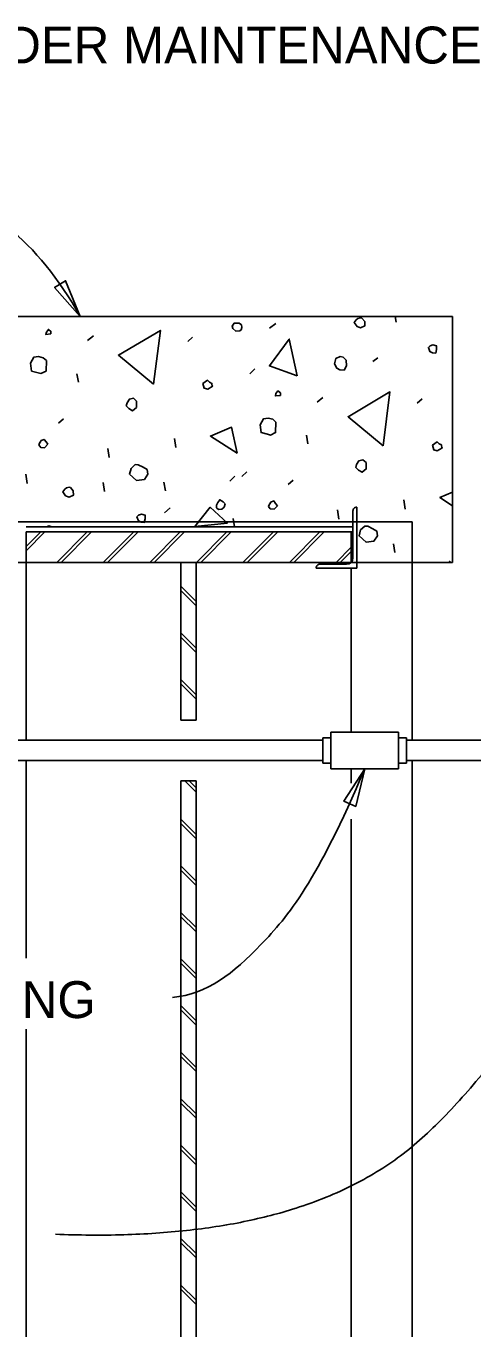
# Model space of a CAD drawing. Extents: x -1660015.2 to -1659984.9, y 2580594.2 to 2580616.7.
# Drawn here: x -1659990.89 to -1659989.06, y 2580599.91 to 2580605.25 of the extents above; entities that cross this region are included whole.
import ezdxf

# ---------------------------------------------------------------- set-up
doc = ezdxf.new("R2010")
doc.units = 0
for name, color, linetype in [('Default', 7, 'Continuous'), ('Miscellaneous', 7, 'Continuous'), ('Miscellaneous3', 7, 'Continuous'), ('PlotBorder_dp', 7, 'Continuous'), ('SheetLines_dp', 7, 'Continuous'), ('SteelGirder', 7, 'Continuous')]:
    doc.layers.add(name, color=color, linetype=linetype)

msp = doc.modelspace()

# ---------------------------------------------------------------- linework, layer by layer
at = {"layer": 'Default'}
for p, q in [((-1659989.3053, 2580603.2147), (-1659991.2021, 2580603.2147)), ((-1659989.3053, 2580603.2147), (-1659989.3053, 2580603.0479)), ((-1659990.8887, 2580603.048), (-1659991.1415, 2580603.048)), ((-1659989.6716, 2580602.3289), (-1659989.6716, 2580602.2247)), ((-1659989.6716, 2580602.3289), (-1659989.6382, 2580602.3289)), ((-1659989.6382, 2580602.3519), (-1659989.6382, 2580602.202)), ((-1659989.6381, 2580602.352), (-1659989.3607, 2580602.352)), ((-1659989.3607, 2580602.3518), (-1659989.3607, 2580602.2019)), ((-1659989.3273, 2580602.3289), (-1659989.3607, 2580602.3289)), ((-1659989.3273, 2580602.3289), (-1659989.3273, 2580602.2247)), ((-1659989.6715, 2580602.3186), (-1659991.6974, 2580602.3186)), ((-1659986.2685, 2580602.3187), (-1659989.3273, 2580602.3187)), ((-1659989.6716, 2580602.2353), (-1659991.6974, 2580602.2353)), ((-1659989.6716, 2580602.2247), (-1659989.6382, 2580602.2247)), ((-1659989.3273, 2580602.2247), (-1659989.3607, 2580602.2247)), ((-1659986.2685, 2580602.2354), (-1659989.3273, 2580602.2354)), ((-1659989.6381, 2580602.2021), (-1659989.3607, 2580602.2021))]:
    msp.add_line(p, q, dxfattribs=at)
at = {"layer": 'Miscellaneous'}
for p, q in [((-1659989.371, 2580604.0323), (-1659989.3744, 2580604.056)), ((-1659990.6126, 2580603.9767), (-1659990.636, 2580603.9571)), ((-1659989.8641, 2580604.0272), (-1659989.8899, 2580604.0082)), ((-1659990.2052, 2580603.9711), (-1659990.2255, 2580603.9532)), ((-1659989.4462, 2580603.8868), (-1659989.4658, 2580603.8713)), ((-1659990.6741, 2580603.7861), (-1659990.6801, 2580603.8214)), ((-1659989.9503, 2580603.8407), (-1659989.9712, 2580603.8204)), ((-1659989.6709, 2580603.7244), (-1659989.6942, 2580603.7048)), ((-1659989.2634, 2580603.7187), (-1659989.2838, 2580603.7009)), ((-1659990.7348, 2580603.6368), (-1659990.7551, 2580603.6189)), ((-1659990.2747, 2580603.5187), (-1659990.2801, 2580603.5563)), ((-1659989.7323, 2580603.5338), (-1659989.7384, 2580603.5691)), ((-1659990.547, 2580603.4778), (-1659990.5525, 2580603.5154)), ((-1659990.8836, 2580603.3712), (-1659990.889, 2580603.4089)), ((-1659990.0317, 2580603.4018), (-1659990.0526, 2580603.3815)), ((-1659989.9828, 2580603.4197), (-1659990.0038, 2580603.3995)), ((-1659990.5664, 2580603.338), (-1659990.5718, 2580603.3757)), ((-1659990.3171, 2580603.3411), (-1659990.3232, 2580603.3764)), ((-1659989.793, 2580603.3844), (-1659989.8133, 2580603.3666)), ((-1659989.3329, 2580603.2663), (-1659989.3383, 2580603.304)), ((-1659990.297, 2580603.271), (-1659990.3204, 2580603.2514)), ((-1659989.6053, 2580603.2254), (-1659989.6107, 2580603.2631)), ((-1659989.5476, 2580603.2591), (-1659989.5476, 2580603.0664)), ((-1659989.532, 2580603.0247), (-1659989.532, 2580603.2747)), ((-1659990.8887, 2580603.1937), (-1659989.5476, 2580603.1937)), ((-1659990.0336, 2580603.1937), (-1659990.0394, 2580603.2279)), ((-1659990.8887, 2580603.1128), (-1659990.8285, 2580603.1729)), ((-1659990.8887, 2580603.0951), (-1659990.8109, 2580603.1729)), ((-1659990.7626, 2580603.0479), (-1659990.6376, 2580603.1729)), ((-1659990.7449, 2580603.0479), (-1659990.6199, 2580603.1729)), ((-1659990.5717, 2580603.0479), (-1659990.4467, 2580603.1729)), ((-1659990.554, 2580603.0479), (-1659990.429, 2580603.1729)), ((-1659990.3808, 2580603.0479), (-1659990.2558, 2580603.1729)), ((-1659990.3631, 2580603.0479), (-1659990.2381, 2580603.1729)), ((-1659990.1899, 2580603.0479), (-1659990.0649, 2580603.1729)), ((-1659990.1722, 2580603.0479), (-1659990.0472, 2580603.1729)), ((-1659989.9989, 2580603.0479), (-1659989.8739, 2580603.1729)), ((-1659989.9813, 2580603.0479), (-1659989.8563, 2580603.1729)), ((-1659989.808, 2580603.0479), (-1659989.683, 2580603.1729)), ((-1659989.7903, 2580603.0479), (-1659989.6653, 2580603.1729)), ((-1659989.5476, 2580603.1729), (-1659989.5553, 2580603.1729)), ((-1659989.3753, 2580603.0887), (-1659989.3814, 2580603.124)), ((-1659989.6171, 2580603.0479), (-1659989.5553, 2580603.1097)), ((-1659989.5994, 2580603.0479), (-1659989.5553, 2580603.0921)), ((-1659989.6987, 2580603.0247), (-1659989.532, 2580603.0247)), ((-1659989.5737, 2580603.0403), (-1659989.683, 2580603.0403)), ((-1659990.1908, 2580602.8874), (-1659990.2531, 2580602.9498)), ((-1659990.1908, 2580602.8697), (-1659990.2531, 2580602.9321)), ((-1659990.1908, 2580602.6965), (-1659990.2531, 2580602.7589)), ((-1659990.1908, 2580602.6788), (-1659990.2531, 2580602.7412)), ((-1659990.1908, 2580602.5056), (-1659990.2531, 2580602.568)), ((-1659990.1908, 2580602.4879), (-1659990.2531, 2580602.5503)), ((-1659990.1908, 2580602.106), (-1659990.2367, 2580602.152)), ((-1659990.1908, 2580602.1237), (-1659990.219, 2580602.152)), ((-1659990.1908, 2580601.9328), (-1659990.2531, 2580601.9952)), ((-1659990.1908, 2580601.9151), (-1659990.2531, 2580601.9775)), ((-1659990.1908, 2580601.7419), (-1659990.2531, 2580601.8043)), ((-1659990.1908, 2580601.7242), (-1659990.2531, 2580601.7866)), ((-1659990.1908, 2580601.551), (-1659990.2531, 2580601.6134)), ((-1659990.1908, 2580601.5333), (-1659990.2531, 2580601.5957)), ((-1659990.1908, 2580601.3601), (-1659990.2531, 2580601.4224)), ((-1659990.1908, 2580601.3424), (-1659990.2531, 2580601.4048)), ((-1659990.1908, 2580601.1691), (-1659990.2531, 2580601.2315)), ((-1659990.1908, 2580601.1515), (-1659990.2531, 2580601.2139)), ((-1659990.1908, 2580600.9782), (-1659990.2531, 2580601.0406)), ((-1659990.1908, 2580600.9605), (-1659990.2531, 2580601.0229)), ((-1659990.1908, 2580600.7873), (-1659990.2531, 2580600.8497)), ((-1659990.1908, 2580600.7696), (-1659990.2531, 2580600.832)), ((-1659990.1908, 2580600.5964), (-1659990.2531, 2580600.6588)), ((-1659990.1908, 2580600.5787), (-1659990.2531, 2580600.6411)), ((-1659990.1908, 2580600.4055), (-1659990.2531, 2580600.4679)), ((-1659990.1908, 2580600.3878), (-1659990.2531, 2580600.4502)), ((-1659990.1908, 2580600.2145), (-1659990.2531, 2580600.2769)), ((-1659990.1908, 2580600.1969), (-1659990.2531, 2580600.2593)), ((-1659990.1908, 2580600.0236), (-1659990.2531, 2580600.086)), ((-1659990.1908, 2580600.0059), (-1659990.2531, 2580600.0683))]:
    msp.add_line(p, q, dxfattribs=at)
for points in [[(-1659989.4995, 2580604.0356), (-1659989.4992, 2580604.0174), (-1659989.5169, 2580604.0092), (-1659989.5307, 2580604.0155), (-1659989.542, 2580604.0315), (-1659989.5339, 2580604.0423), (-1659989.5271, 2580604.0482), (-1659989.5162, 2580604.0505), (-1659989.5114, 2580604.0492), (-1659989.4995, 2580604.0356)], [(-1659990.7866, 2580603.9845), (-1659990.8078, 2580603.9824), (-1659990.8052, 2580603.9921), (-1659990.7972, 2580604.0029), (-1659990.7864, 2580603.9948), (-1659990.7866, 2580603.9845)], [(-1659990.3655, 2580603.7785), (-1659990.3376, 2580603.9988), (-1659990.5097, 2580603.8974), (-1659990.3655, 2580603.7785)], [(-1659990.0058, 2580604.0005), (-1659990.0119, 2580603.9969), (-1659990.0277, 2580603.996), (-1659990.0403, 2580604.0071), (-1659990.0432, 2580604.0157), (-1659990.0344, 2580604.0289), (-1659990.0138, 2580604.0285), (-1659990.0055, 2580604.0211), (-1659990.0032, 2580604.0101), (-1659990.0058, 2580604.0005)], [(-1659989.7767, 2580603.8123), (-1659989.8087, 2580603.9632), (-1659989.89, 2580603.853), (-1659989.7767, 2580603.8123)], [(-1659989.2043, 2580603.9203), (-1659989.2081, 2580603.9058), (-1659989.2209, 2580603.9066), (-1659989.2323, 2580603.9123), (-1659989.2381, 2580603.9293), (-1659989.2313, 2580603.9353), (-1659989.2197, 2580603.94), (-1659989.2052, 2580603.9361), (-1659989.2043, 2580603.9203)], [(-1659990.8054, 2580603.8757), (-1659990.8067, 2580603.832), (-1659990.8275, 2580603.8221), (-1659990.8396, 2580603.8253), (-1659990.8661, 2580603.8324), (-1659990.8704, 2580603.8646), (-1659990.8561, 2580603.8893), (-1659990.8372, 2580603.892), (-1659990.8179, 2580603.8868), (-1659990.8054, 2580603.8757)], [(-1659989.5755, 2580603.8774), (-1659989.5741, 2580603.8537), (-1659989.5841, 2580603.8357), (-1659989.6016, 2580603.8378), (-1659989.6131, 2580603.8435), (-1659989.6237, 2580603.8619), (-1659989.6179, 2580603.8836), (-1659989.6001, 2580603.8918), (-1659989.5881, 2580603.8885), (-1659989.5755, 2580603.8774)], [(-1659990.1249, 2580603.7684), (-1659990.1433, 2580603.7578), (-1659990.1578, 2580603.7617), (-1659990.1629, 2580603.7812), (-1659990.1439, 2580603.7942), (-1659990.1355, 2580603.7868), (-1659990.1265, 2580603.7818), (-1659990.1249, 2580603.7684), (-1659990.1236, 2580603.7732)], [(-1659990.4353, 2580603.7015), (-1659990.435, 2580603.6833), (-1659990.4516, 2580603.6696), (-1659990.4673, 2580603.679), (-1659990.4774, 2580603.6894), (-1659990.4742, 2580603.7015), (-1659990.4648, 2580603.7171), (-1659990.4484, 2580603.7205), (-1659990.4358, 2580603.7094), (-1659990.4353, 2580603.7015)], [(-1659989.8448, 2580603.7322), (-1659989.866, 2580603.7301), (-1659989.8634, 2580603.7397), (-1659989.8554, 2580603.7505), (-1659989.8446, 2580603.7425), (-1659989.8448, 2580603.7322)], [(-1659989.4237, 2580603.5262), (-1659989.3958, 2580603.7464), (-1659989.5679, 2580603.645), (-1659989.4237, 2580603.5262)], [(-1659989.8636, 2580603.6233), (-1659989.8649, 2580603.5797), (-1659989.8857, 2580603.5697), (-1659989.8978, 2580603.573), (-1659989.9243, 2580603.5801), (-1659989.9287, 2580603.6123), (-1659989.9143, 2580603.6369), (-1659989.8955, 2580603.6396), (-1659989.8761, 2580603.6344), (-1659989.8636, 2580603.6233)], [(-1659990.799, 2580603.5323), (-1659990.8132, 2580603.518), (-1659990.8283, 2580603.5195), (-1659990.8361, 2580603.5293), (-1659990.8348, 2580603.5341), (-1659990.826, 2580603.5473), (-1659990.8144, 2580603.552), (-1659990.8067, 2580603.5422), (-1659990.799, 2580603.5323)], [(-1659990.0222, 2580603.495), (-1659990.0453, 2580603.6021), (-1659990.1326, 2580603.566), (-1659990.0222, 2580603.495)], [(-1659989.1832, 2580603.5161), (-1659989.2015, 2580603.5055), (-1659989.216, 2580603.5093), (-1659989.2212, 2580603.5288), (-1659989.2021, 2580603.5418), (-1659989.1938, 2580603.5344), (-1659989.1848, 2580603.5294), (-1659989.1832, 2580603.5161), (-1659989.1819, 2580603.5209)], [(-1659990.3893, 2580603.4096), (-1659990.403, 2580603.3874), (-1659990.4352, 2580603.3831), (-1659990.4645, 2580603.4091), (-1659990.458, 2580603.4332), (-1659990.4408, 2580603.4493), (-1659990.4281, 2580603.4485), (-1659990.4076, 2580603.4378), (-1659990.392, 2580603.4284), (-1659990.3893, 2580603.4096)], [(-1659989.4936, 2580603.4491), (-1659989.4933, 2580603.4309), (-1659989.5099, 2580603.4172), (-1659989.5255, 2580603.4266), (-1659989.5356, 2580603.4371), (-1659989.5324, 2580603.4492), (-1659989.523, 2580603.4648), (-1659989.5066, 2580603.4681), (-1659989.494, 2580603.457), (-1659989.4936, 2580603.4491)], [(-1659990.6949, 2580603.3414), (-1659990.6946, 2580603.3232), (-1659990.7123, 2580603.315), (-1659990.7262, 2580603.3213), (-1659990.7374, 2580603.3372), (-1659990.7293, 2580603.348), (-1659990.7226, 2580603.354), (-1659990.7116, 2580603.3562), (-1659990.7068, 2580603.3549), (-1659990.6949, 2580603.3414)], [(-1659989.1387, 2580603.3352), (-1659989.1908, 2580603.3136), (-1659989.1387, 2580603.2801)], [(-1659990.0763, 2580603.274), (-1659990.0861, 2580603.2662), (-1659990.0995, 2580603.2646), (-1659990.1078, 2580603.2721), (-1659990.1076, 2580603.2824), (-1659990.102, 2580603.2938), (-1659990.0939, 2580603.3046), (-1659990.0807, 2580603.2959), (-1659990.0724, 2580603.2884), (-1659990.0763, 2580603.274)], [(-1659989.8572, 2580603.28), (-1659989.8714, 2580603.2657), (-1659989.8866, 2580603.2671), (-1659989.8943, 2580603.277), (-1659989.893, 2580603.2818), (-1659989.8843, 2580603.295), (-1659989.8727, 2580603.2996), (-1659989.865, 2580603.2898), (-1659989.8572, 2580603.28)], [(-1659990.3997, 2580603.226), (-1659990.4036, 2580603.2115), (-1659990.4163, 2580603.2124), (-1659990.4277, 2580603.218), (-1659990.4335, 2580603.2351), (-1659990.4267, 2580603.241), (-1659990.4151, 2580603.2457), (-1659990.4006, 2580603.2418), (-1659990.3997, 2580603.226)], [(-1659990.0628, 2580603.2082), (-1659990.1333, 2580603.2737), (-1659990.1958, 2580603.1947), (-1659990.0628, 2580603.2082)], [(-1659990.8037, 2580603.1937), (-1659990.7955, 2580603.1975), (-1659990.7835, 2580603.1943), (-1659990.7829, 2580603.1937)], [(-1659989.4475, 2580603.1573), (-1659989.4613, 2580603.135), (-1659989.4935, 2580603.1307), (-1659989.5227, 2580603.1567), (-1659989.5163, 2580603.1809), (-1659989.499, 2580603.1969), (-1659989.4863, 2580603.1961), (-1659989.4659, 2580603.1855), (-1659989.4503, 2580603.1761), (-1659989.4475, 2580603.1573)], [(-1659989.1554, 2580603.0479), (-1659989.1522, 2580603.0522), (-1659989.1456, 2580603.0479)]]:
    msp.add_lwpolyline(points, dxfattribs=at)
for centre, radius, start, end in [((-1659989.532, 2580603.2591), 0.0156, 90.0047, 180.0047), ((-1659989.683, 2580603.0247), 0.0156, 90.0047, 180.0047), ((-1659989.5737, 2580603.0663), 0.026, 270.0047, 0.0047)]:
    msp.add_arc(centre, radius, start, end, dxfattribs=at)
at = {"layer": 'Miscellaneous3'}
for p, q in [((-1659989.1387, 2580604.056), (-1659992.6544, 2580604.056)), ((-1659989.1387, 2580603.0479), (-1659989.1387, 2580604.056)), ((-1659989.1387, 2580603.0479), (-1659989.3053, 2580603.0479))]:
    msp.add_line(p, q, dxfattribs=at)
at = {"layer": 'SheetLines_dp'}
for points in [[(-1659990.6667, 2580604.0559), (-1659990.7713, 2580604.1748), (-1659990.7263, 2580604.2026)], [(-1659989.4994, 2580602.2021), (-1659989.5848, 2580602.0687), (-1659989.5361, 2580602.048)]]:
    msp.add_lwpolyline(points, close=True, dxfattribs=at)
msp.add_ellipse((-1659991.4118, 2580602.1871), major_axis=(-0.1111, -2.3674), ratio=0.464296, start_param=2.502126, end_param=3.141581, dxfattribs=at)
for points, degree in [([(-1659990.7679, 2580600.2937), (-1659989.7598, 2580600.2551), (-1659988.8041, 2580601.0904), (-1659988.2709, 2580602.1865)], 2), ([(-1659990.288, 2580601.265), (-1659990.1447, 2580601.2764), (-1659989.9308, 2580601.4539), (-1659989.6944, 2580601.7407), (-1659989.4994, 2580602.2021)], 3)]:
    msp.add_open_spline(points, degree=degree, dxfattribs=at)
at = {"layer": 'SteelGirder'}
for p, q in [((-1659990.8887, 2580603.1729), (-1659989.5553, 2580603.1729)), ((-1659990.8887, 2580603.0247), (-1659990.8887, 2580603.1729)), ((-1659989.5553, 2580603.0479), (-1659989.5553, 2580603.1729)), ((-1659990.8887, 2580603.0479), (-1659989.3053, 2580603.0479)), ((-1659990.8887, 2580602.3186), (-1659990.8887, 2580603.0247)), ((-1659990.2532, 2580602.4019), (-1659990.2532, 2580603.0479)), ((-1659990.1908, 2580602.4019), (-1659990.1908, 2580603.0479)), ((-1659989.5553, 2580602.352), (-1659989.5553, 2580603.0247)), ((-1659989.3053, 2580602.3187), (-1659989.3053, 2580603.0479)), ((-1659990.1908, 2580602.4019), (-1659990.2532, 2580602.4019)), ((-1659990.8887, 2580601.4262), (-1659990.8887, 2580602.2353)), ((-1659989.3053, 2580597.7672), (-1659989.3053, 2580602.2354)), ((-1659989.5553, 2580602.1433), (-1659989.5553, 2580602.2021)), ((-1659990.2532, 2580597.7672), (-1659990.2532, 2580602.152)), ((-1659990.1908, 2580602.152), (-1659990.2532, 2580602.152)), ((-1659990.1908, 2580597.7672), (-1659990.1908, 2580602.152)), ((-1659989.5553, 2580597.7672), (-1659989.5553, 2580601.9948)), ((-1659990.8887, 2580597.7672), (-1659990.8887, 2580601.1344))]:
    msp.add_line(p, q, dxfattribs=at)

# ---------------------------------------------------------------- texts
at = {"layer": 'PlotBorder_dp'}
msp.add_text('EXPANSION FITTING', height=0.1512, dxfattribs=at).set_placement((-1659992.625, 2580601.1801))
at = {"layer": 'SheetLines_dp'}
msp.add_text('1.  FOR BOX GIRDER MAINTENANCE LIGHTING NOTES SEE SHEET 1.', height=0.1512, dxfattribs=at).set_placement((-1659992.5804, 2580605.0929))

doc.saveas('drawing.dxf')
